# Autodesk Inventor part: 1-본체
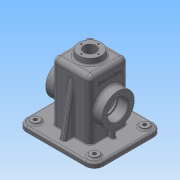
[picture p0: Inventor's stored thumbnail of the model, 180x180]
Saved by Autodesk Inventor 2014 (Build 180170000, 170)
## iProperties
Created: 2015-12
Part Number: 1-본체
Material: Generic
Document SubType Name: Modeling
Designer: Administrator
Density: 1 g/cm^3
Appearance: Default
Author: Administrator
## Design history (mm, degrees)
sketch "스케치1"
  geometry: L1 (65, -57.5)-(-65, -57.5); L2 (-65, -57.5)-(-65, 57.5); L3 (-65, 57.5)-(65, 57.5); L4 (65, 57.5)-(65, -57.5); L5 (65, -57.5)-(-65, 57.5); L6 (-65, -57.5)-(65, 57.5); 1 further point
  constraints: 12 end point, 2 midpoint, 2 parallel, 1 horizontal, 1 perpendicular
  dimensions: "d0" = 130 distance of L2.end L3.end; "d1" = 115 distance of L3.end L1.start
extrude "돌출1" new body sketch "스케치1" distance "d2" = 8; taper "d3" = 0 deg
node "작업 평면2"
sketch "스케치3"
  geometry: L1 (32.5, -32.5)-(-32.5, -32.5); L2 (-32.5, -32.5)-(-32.5, 32.5); L3 (-32.5, 32.5)-(32.5, 32.5); L4 (32.5, 32.5)-(32.5, -32.5); L5 (32.5, -32.5)-(-32.5, 32.5); L6 (-32.5, -32.5)-(32.5, 32.5); 1 further point
  constraints: 12 end point, 2 midpoint, 2 parallel, 1 horizontal, 1 perpendicular
  dimensions: "d6" = 65 distance of L2.end L3.end; "d7" = 65 distance of L3.end L1.start
extrude "돌출2" join sketch "스케치3" stored distance "d8" = 10; taper "d9" = 0 deg
node "작업 평면5"
sketch "스케치6"
  geometry: L1 (-32.5, 108)-(-32.5, 8) reference; L2 (-57.5, 0)-(-57.5, 8) reference; L3 (57.5, 8)-(-57.5, 8) reference; L4 (-47.5, 8)-(-31.058, 101.247); L5 (-31.058, 101.247)-(-31.058, 8); L6 (-47.5, 8)-(-31.058, 8); 1 further point
  constraints: 6 end point, 2 point on line, 1 collinear, 1 perpendicular
  dimensions: "d21" = 10 distance from line of L4.start L2; "d22" = 10 deg angle of L4 L2; "d23" = 93.24685 distance of L4.end L5.end
extrude "돌출3" join sketch "스케치6" stored distance "d24" = 10; taper "d25" = 0 deg
sketch "스케치7"
  geometry: L1 (60, -52.5)-(-60, -52.5); L2 (-60, -52.5)-(-60, 52.5); L3 (-60, 52.5)-(60, 52.5); L4 (60, 52.5)-(60, -52.5); L5 (60, -52.5)-(-60, 52.5); L6 (-60, -52.5)-(60, 52.5); 1 further point
  constraints: 12 end point, 2 midpoint, 2 parallel, 1 horizontal, 1 perpendicular
  dimensions: "d26" = 120 distance of L2.end L3.end; "d27" = 105 distance of L3.end L1.start
extrude "돌출4" join sketch "스케치7" distance "d28" = 2; taper "d29" = 0 deg
node "작업 평면6"
node "작업 평면7"
sketch "스케치9"
  geometry: L1 (-32.5, 108)-(-32.5, 8) reference; L2 (32.5, 108)-(32.5, 8) reference; L3 (-32.5, 108)-(32.5, 108) reference; L4 (27.5, -2)-(27.5, 103); L5 (27.5, 103)-(-27.5, 103); L6 (-27.5, 103)-(-27.5, -2); L7 (-52.5, -2)-(52.5, -2) reference; 1 further point
  constraints: 6 end point, 2 point on line
  dimensions: "d36" = 5 distance between parallel lines of L6 L1; "d37" = 5 distance between parallel lines of L2 L4; "d38" = 5 distance between parallel lines of L5 L3
extrude "돌출5" cut sketch "스케치9" stored distance "d39" = 55; taper "d40" = 0 deg
node "작업 평면10"
node "작업 평면8"
sketch "스케치22"
  geometry: C1 r 20 at (0, 0); 1 further point
  constraints: 1 centre point, 1 coincident
  dimensions: "d176" = 40 diameter of C1
extrude "돌출12" join sketch "스케치22" distance "d177" = 10; taper "d178" = -5 deg
node "작업 평면9"
fillet "모깎기1" dims "d71" = 15
sketch "스케치15"
  geometry: C1 r 7.5 at (-50, 42.5); C2 r 7.5 at (-50, -42.5); A1 r 15 centre (-50, 42.5) between (-50, 57.5) and (-65, 42.5) reference; A2 r 15 centre (-50, -42.5) between (-65, -42.5) and (-50, -57.5) reference; 1 further point
  constraints: 2 centre point, 2 coincident, 1 equal radius
  dimensions: "d72" = 15 diameter of C1
extrude "돌출9" join sketch "스케치15" distance "d73" = 3; taper "d74" = 0 deg
hole "구멍3" diameter "d77" = 6; stored, may be unused: countersink angle "d81" = 90 deg, drill point angle "d83" = 118 deg; dims "d75" = 10, "d76" = 10, "d78" = 8, "d79" = 35, "d80" = 17, "d82" = 10
hole "구멍4" diameter "d86" = 6; stored, may be unused: countersink angle "d90" = 90 deg, drill point angle "d92" = 118 deg; dims "d84" = 10, "d85" = 10, "d87" = 8, "d88" = 35, "d89" = 17, "d91" = 10
sketch "스케치17"
  geometry: L1 (0, 0)-(100, 0) reference; L2 (-10, 13.375)-(-10, 51.625) reference; 2 further points
  constraints: 1 other
  dimensions: "d103" = 32.5 distance from line of point (16, 32.5) L1; "d196" = 26 distance from line of point (16, 32.5) L2
feature "엠보싱1" sketch "스케치17" dims "d104" = 0.5, "d105" = 0
fillet "모깎기4" dims "d116" = 10
fillet "모깎기8" dims "d125" = 3
fillet "모깎기9" dims "d126" = 1
fillet "모깎기12" dims "d129" = 3
fillet "모깎기13" dims "d130" = 3
fillet "모깎기14" dims "d131" = 3
fillet "모깎기16" dims "d133" = 8
fillet "모깎기17" dims "d134" = 8
sketch "스케치19"
  geometry: L1 (-110, -20)-(-110, 85) reference; L2 (0, 0)-(0, 65) reference; C1 r 27.5 at (-55, 32.5); 2 further points
  constraints: 1 centre point, 1 horizontal alignment, 1 midpoint
  dimensions: "d136" = 55 distance from line of L1 C1.centre; "d137" = 55 diameter of C1
extrude "돌출10" join sketch "스케치19" stored distance "d138" = 3; taper "d139" = 0 deg
hole "구멍7" diameter "d142" = 30; stored, may be unused: countersink angle "d146" = 90 deg, drill point angle "d148" = 0 deg; dims "d143" = 7, "d144" = 35, "d145" = 17, "d147" = 20, "d150" = 10, "d151" = 10
sketch "스케치20"
  geometry: C1 r 17.5 at (0, 0) reference; C2 r 27.5 at (0, 0) reference; A1 r 21 centre (0, 0) between (21, 0) and (0, -21); 3 further points
  constraints: 4 point on circle, 2 horizontal alignment, 2 vertical alignment, 1 centre point, 1 coincident
  dimensions: "d149" = 42 diameter of A1
hole "구멍8" sketch "스케치20" at (21, 0), (0, -21), (-21, 0), (0, 21) diameter "d152" = 3.242; stored, may be unused: countersink angle "d156" = 90 deg, drill point angle "d158" = 118 deg; dims "d153" = 8, "d154" = 42, "d155" = 17, "d157" = 10
fillet "모깎기18" dims "d159" = 3
fillet "모깎기19" dims "d160" = 3
fillet "모깎기20" dims "d161" = 0.3
node "작업 평면11"
sketch "스케치21"
  geometry: L1 (-47.5, 25.5)-(-35.5, 25.5) reference; L2 (-32.5, 9)-(-32.5, 34.834) reference; L3 (-50, 8)-(50, 8) reference; L4 (-42.5, 8)-(-42.5, 26.353); L5 (-42.5, 26.353)-(-28.993, 26.353); L6 (-28.993, 26.353)-(-28.993, 8); L7 (-42.5, 8)-(-28.993, 8); L8 (-27.5, 100)-(-27.5, -2) reference; A1 r 3 centre (-35.5, 22.5) between (-32.5, 22.5) and (-35.5, 25.5) reference; 2 further points
  constraints: 8 end point, 3 perpendicular, 2 point on line, 1 collinear
  dimensions: "d163" = 15 distance between parallel lines of L4 L8; "d164" = 18.35318 distance of L4.start L4.end; "d171" = 13.50681 distance of L4.end L5.end
extrude "돌출11" join sketch "스케치21" stored distance "d166" = 6; taper "d167" = 0 deg
fillet "모깎기21" dims "d168" = 3
fillet "모깎기22" dims "d169" = 1
fillet "모깎기24" dims "d172" = 1
chamfer "모따기2" distance "d173" = 1; stored, may be unused: second distance "d174" = 2, angle "d175" = 45 deg
sketch "스케치23"
  geometry: C1 r 19.125 at (0, 0) reference; A1 r 14.5 centre (0, 0) between (0, 14.5) and (14.5, 0); 2 further points
  constraints: 4 point on circle, 2 horizontal alignment, 2 vertical alignment, 1 centre point, 1 coincident
  dimensions: "d179" = 29 diameter of A1
hole "구멍9" sketch "스케치23" at (0, 14.5), (14.5, 0), (-14.5, 0), (0, -14.5) diameter "d180" = 2.459; stored, may be unused: countersink angle "d184" = 90 deg, drill point angle "d186" = 118 deg; dims "d181" = 7, "d182" = 42, "d183" = 17, "d185" = 9
hole "구멍10" diameter "d189" = 21; stored, may be unused: countersink angle "d193" = 90 deg, drill point angle "d195" = 118 deg; dims "d187" = 10, "d188" = 10, "d190" = 7, "d191" = 42, "d192" = 17, "d194" = 9
fillet "모깎기25" dims "d197" = 3
node "솔리드1"
mirror "대칭1"
mirror "대칭4"
mirror "대칭5"
mirror "대칭6"
other parameters: "d5" = 108, "d17" = 0, "d30" = 0, "d35" = 0, "d66" = 0, "d135" = 15, "d162" = 0
